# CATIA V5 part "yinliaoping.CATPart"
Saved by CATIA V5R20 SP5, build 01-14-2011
Part number: 饮料瓶
Material "Bathroom Floor": density 2770 kg/m3, Young's modulus 6e+10 Pa, Poisson ratio 0.3
Material "Bathroom Floor": density 2770 kg/m3, Young's modulus 6e+10 Pa, Poisson ratio 0.3
Bounding box of the stored display mesh (mm): x -25 to 25, y -25 to 25, z -60 to 50
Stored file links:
  E:\画图\yinliaoping.CATPart
  C:\Program Files\Dassault Systemes\B20\intel_a\startup\materials\Catalog.CATMaterial
  C:\Program Files\Dassault Systemes\B20\intel_a\startup\materials\DS_star.jpg
  C:\Program Files\Dassault Systemes\B20\intel_a\startup\materials\pink_marble.jpg
  C:\Program Files\Dassault Systemes\B20\intel_a\startup\materials\marble.jpg
  C:\Program Files\Dassault Systemes\B20\intel_a\startup\materials\slate.jpg
  C:\Program Files\Dassault Systemes\B20\intel_a\startup\materials\marble_tile.jpg
  C:\Program Files\Dassault Systemes\B20\intel_a\startup\materials\brown_onyx.jpg
  C:\Program Files\Dassault Systemes\B20\intel_a\startup\materials\green_leather.jpg
  C:\Program Files\Dassault Systemes\B20\intel_a\startup\materials\red_leather.jpg
  C:\Program Files\Dassault Systemes\B20\intel_a\startup\materials\sponge.jpg
  C:\Program Files\Dassault Systemes\B20\intel_a\startup\materials\concrete.jpg
  C:\Program Files\Dassault Systemes\B20\intel_a\startup\materials\yellow_env_512x512.jpg
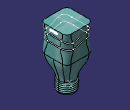
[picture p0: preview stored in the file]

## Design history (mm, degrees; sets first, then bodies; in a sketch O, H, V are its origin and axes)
Set1
  Sketch1 on xy-plane, origin (0, 0, 0), H (1, 0, 0), V (0, 1, 0)
    line L1 (25, 25) -> (25, -25)
    line L2 (25, -25) -> (-25, -25)
    line L3 (-25, -25) -> (-25, 25)
    line L4 (-25, 25) -> (25, 25)
    length L4 = 50
    length L1 = 50
    vertical: L1 V, L3 V
    horizontal: L2 H, L4 H
    equidistance: L1 L3 O, L2 L4 O
  Sketch2 on face of Pad1 from Sketch1.L4, origin (0, 25, 0), H (-1, 0, 0), V (0, 0, 1)
    spline S1 through (-29.1865, 41.6292) (-8.3041, 33.7288) (7.8663, 39.921) (28.4274, 34.3694)
  Extrude1: Element1 Sketch2, Lim1 23, Lim2 70
  MultiSel1: CommonCtxFeats ({extract ExtractElem face of Pad1 from Sketch1.L1}; {extract ExtractElem face of Fillet1}; {extract ExtractElem face of Pad1 from Sketch1.L4}; {extract ExtractElem face of Fillet1}; {extract ExtractElem face of Pad1 from Sketch1.L3}; {extract ExtractElem face of Fillet1}; {extract ExtractElem face of Pad1 from Sketch1.L2}; {extract ExtractElem face of Fillet1})
  Sketch3 on face of Pad1 from Sketch1.L2, origin (0, -25, 0), H (1, 0, 0), V (0, 0, 1)
    spline S1 through (-28.2052, 22.5491) (-17.1443, 28.5221) (0, 24.8464) (11.8904, 22.5491) (30.0947, 26.6843)
    point P1 (0, 24.8464)
    coincidence: P1 V
  Extrude2: Element1 Sketch3, Lim1 55, Lim2 55
  MultiSel2: CommonCtxFeats ({extract ExtractElem face of Fillet1}; {extract ExtractElem face of Pad1 from Sketch1.L2}; {extract ExtractElem face of Fillet1}; {extract ExtractElem face of Pad1 from Sketch1.L1}; {extract ExtractElem face of Fillet1}; {extract ExtractElem face of Pad1 from Sketch1.L4}; {extract ExtractElem face of Fillet1}; {extract ExtractElem face of Pad1 from Sketch1.L3})
  Join1: Elements ({intersect ToIntersect1 {extract ExtractElem face of Pad1 from Sketch1.L1}, ToIntersect2 Extrude1}; {intersect ToIntersect1 {extract ExtractElem face of Fillet1}, ToIntersect2 Extrude1}; {intersect ToIntersect1 {extract ExtractElem face of Pad1 from Sketch1.L4}, ToIntersect2 Extrude1}; {intersect ToIntersect1 {extract ExtractElem face of Fillet1}, ToIntersect2 Extrude1}; {intersect ToIntersect1 {extract ExtractElem face of Pad1 from Sketch1.L3}, ToIntersect2 Extrude1}; {intersect ToIntersect1 {extract ExtractElem face of Fillet1}, ToIntersect2 Extrude1}; {intersect ToIntersect1 {extract ExtractElem face of Pad1 from Sketch1.L2}, ToIntersect2 Extrude1}; {intersect ToIntersect1 {extract ExtractElem face of Fillet1}, ToIntersect2 Extrude1})
  Join2: Elements ({intersect ToIntersect1 {extract ExtractElem face of Fillet1}, ToIntersect2 Extrude2}; {intersect ToIntersect1 {extract ExtractElem face of Pad1 from Sketch1.L2}, ToIntersect2 Extrude2}; {intersect ToIntersect1 {extract ExtractElem face of Fillet1}, ToIntersect2 Extrude2}; {intersect ToIntersect1 {extract ExtractElem face of Pad1 from Sketch1.L1}, ToIntersect2 Extrude2}; {intersect ToIntersect1 {extract ExtractElem face of Fillet1}, ToIntersect2 Extrude2}; {intersect ToIntersect1 {extract ExtractElem face of Pad1 from Sketch1.L4}, ToIntersect2 Extrude2}; {intersect ToIntersect1 {extract ExtractElem face of Fillet1}, ToIntersect2 Extrude2}; {intersect ToIntersect1 {extract ExtractElem face of Pad1 from Sketch1.L3}, ToIntersect2 Extrude2})
  Join3: Elements ({intersect ToIntersect1 {extract ExtractElem face of Pad1 from Sketch1.L1}, ToIntersect2 Extrude1}; {intersect ToIntersect1 {extract ExtractElem face of Fillet1}, ToIntersect2 Extrude1}; {intersect ToIntersect1 {extract ExtractElem face of Pad1 from Sketch1.L4}, ToIntersect2 Extrude1}; {intersect ToIntersect1 {extract ExtractElem face of Fillet1}, ToIntersect2 Extrude1}; {intersect ToIntersect1 {extract ExtractElem face of Pad1 from Sketch1.L3}, ToIntersect2 Extrude1}; {intersect ToIntersect1 {extract ExtractElem face of Fillet1}, ToIntersect2 Extrude1}; {intersect ToIntersect1 {extract ExtractElem face of Pad1 from Sketch1.L2}, ToIntersect2 Extrude1}; {intersect ToIntersect1 {extract ExtractElem face of Fillet1}, ToIntersect2 Extrude1})
  Join4: Elements ({intersect ToIntersect1 {extract ExtractElem face of Fillet1}, ToIntersect2 Extrude2}; {intersect ToIntersect1 {extract ExtractElem face of Pad1 from Sketch1.L2}, ToIntersect2 Extrude2}; {intersect ToIntersect1 {extract ExtractElem face of Fillet1}, ToIntersect2 Extrude2}; {intersect ToIntersect1 {extract ExtractElem face of Pad1 from Sketch1.L1}, ToIntersect2 Extrude2}; {intersect ToIntersect1 {extract ExtractElem face of Fillet1}, ToIntersect2 Extrude2}; {intersect ToIntersect1 {extract ExtractElem face of Pad1 from Sketch1.L4}, ToIntersect2 Extrude2}; {intersect ToIntersect1 {extract ExtractElem face of Fillet1}, ToIntersect2 Extrude2}; {intersect ToIntersect1 {extract ExtractElem face of Pad1 from Sketch1.L3}, ToIntersect2 Extrude2})
  Plane1: type Normal, Curve Join3, RefPoint vertex [face of MultiSel1 | face of MultiSel1]
  Plane2: type Normal, Curve Join4, RefPoint vertex [face of MultiSel2 | face of MultiSel2]
  Sketch4 on Plane2, origin (11.4121, 0, -0.4084), H (0, 1, 0), V (0.0358, 0, 0.9994)
    circle A1 centre (25.1441, 22.9699) radius 1
    radius A1 = 1
  Sketch5 on Plane1, origin (13.8067, 0, 0.1819), H (0, -1, 0), V (-0.0132, 0, 0.9999)
    circle A1 centre (-25.2283, 32.8031) radius 1
    radius A1 = 1
Body1 (main body), material "Bathroom Floor"
  Pad1: profile Sketch1, direction (0, 0, 1), length 50
  Fillet1: on edge [face of Pad1 from Sketch1.L4 | face of Pad1 from Sketch1.L1]; edge [face of Pad1 from Sketch1.L3 | face of Pad1 from Sketch1.L4]; edge [face of Pad1 from Sketch1.L1 | face of Pad1 from Sketch1.L2]; edge [face of Pad1 from Sketch1.L2 | face of Pad1 from Sketch1.L3]
  Plane3: type Offset, RefPlane xy-plane, Offset 40, reversed
  Sketch6 on Plane3, origin (0, 0, -40), H (1, 0, 0), V (0, 1, 0)
    circle A1 centre (0, 0) radius 15
    radius A1 = 15
  Pad2: profile Sketch6, direction (0, 0, -1), length 20
  Sketch7 on start face of Pad1, origin (0, 0, 0), H (1, 0, 0), V (0, -1, 0)
  Sketch8 on start face of Pad1, origin (0, 0, 0), H (1, 0, 0), V (0, -1, 0)
  Sketch9 on start face of Pad1, origin (0, 0, 0), H (1, 0, 0), V (0, -1, 0)
    point P1 (25, 0)
    distance P1 V = 25
    coincidence: P1 H
  Sketch10 on Plane3, origin (0, 0, -40), H (1, 0, 0), V (0, 1, 0)
    point P1 (15, 0)
    distance P1 V = 15
    coincidence: P1 H
  Loft1: solid, Sections ({boundary Boundary {extract ExtractElem start face of Pad1}}; {boundary Boundary {extract ExtractElem start face of Pad2}}), StartFace start face of Pad1, EndFace start face of Pad2
  Slot1: profile Sketch5, centre curve Join3
  Slot2: profile Sketch4, centre curve Join4
  Shell1: ExtOffset 0, Face end face of Pad2, IntOffset 1
  Plane4: type Offset, RefPlane Plane3, Offset 2, reversed
  Sketch11 on Plane4, origin (0, 0, -42), H (1, 0, 0), V (0, 1, 0)
    point P1 (15, 0)
    distance P1 O = 15
    coincidence: P1 H
  Sketch12 on Plane4, origin (0, 0, -42), H (1, 0, 0), V (0, 1, 0)
  Helix1: Direction Z axis, RefPoint Sketch11, Pitch 3, Height 16, TaperAngle 0
  Line1: type Tangency, RefPoint vertex of Helix1, Curve Helix1, Start 0, End 10
  Point1: (10, 10, 0), relative to vertex of Line1
  Line2: type PtPt, FirstPoint Point1, SecondPoint vertex of Line1
  Connect1: Curve1 Line2, Point1 Point1, Tension1 1, Curve2 Line1, Point2 vertex of Helix1, Tension2 1
  Point2: (0, 10, 0), relative to Sketch11
  Point3: (-10, 0, 0), relative to Point2
  Line3: type PtPt, FirstPoint Sketch11, SecondPoint Point2
  Line4: type PtPt, FirstPoint Point2, SecondPoint Point3
  Connect2: Curve1 Line4, Point1 Point3, Tension1 1, Curve2 Line3, Point2 Sketch11, Tension2 1
Body2, material "Bathroom Floor"
  Sketch13 on face of Pad1 from Sketch1.L1, origin (25, 0, 0), H (0, 1, 0), V (0, 0, 1)
    polyline C1
    polyline C2
    polyline C3
    polyline C4
    polyline C5
    polyline C6
    polyline C7
    polyline C8
    polyline C9
    polyline C10
    polyline C11
    polyline C12
    polyline C13
    polyline C14
    polyline C15
    polyline C16
    polyline C17
    polyline C18
    polyline C19
    polyline C20
    polyline C21
    polyline C22
    polyline C23
    polyline C24
    polyline C25
    polyline C26
    polyline C27
    polyline C28
    polyline C29
    polyline C30
    polyline C31
    polyline C32
    polyline C33
    polyline C34
    polyline C35
    polyline C36
    polyline C37
    polyline C38
    polyline C39
    polyline C40
    polyline C41
    polyline C42
    polyline C43
    polyline C44
    polyline C45
    polyline C46
    polyline C47
    polyline C48
    polyline C49
    polyline C50
    polyline C51
    polyline C52
    polyline C53
    polyline C54
    polyline C55
    polyline C56
    polyline C57
    polyline C58
    polyline C59
    polyline C60
    polyline C61
    polyline C62
    polyline C63
    polyline C64
    polyline C65
    polyline C66
  Plane5: type Normal, Curve Helix1, RefPoint Sketch11
  Sketch14 on Plane5, origin (0, -1.3355, -0.0425), H (1, 0, 0), V (0, -0.0318, 0.9995)
    circle A1 centre (15.0848, -41.933) radius 1
    radius A1 = 1
  Rib1: profile Sketch14, centre curve Helix1
  Plane6: type Normal, Curve Connect1, RefPoint Point1
  Sketch15 on Plane6, origin (-2.0744, -2.0744, 0), H (0.7071, -0.7071, 0), V (0, 0, 1)
    circle A1 centre (-5.7505, -58.3805) radius 1
    radius A1 = 1
  Rib2: profile Sketch15, centre curve Connect1
  Plane7: type Normal, Curve Connect2, RefPoint Point3
  Sketch16 on Plane7, origin (5, 0, 0), H (0, -1, 0), V (0, 0, 1)
    circle A1 centre (-10.0777, -42.0717) radius 1
    radius A1 = 1
  Rib3: profile Sketch16, centre curve Connect2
